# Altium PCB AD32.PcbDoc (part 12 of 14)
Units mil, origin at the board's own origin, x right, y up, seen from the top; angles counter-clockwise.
Board outline 7007.87 x 4368.85 mil, 12 copper layers (Top Layer, Int1 (GND), Int2 (AVDD), Int3 (DVDD), Int4 (GND), Int5 (ST), Int6 (SB), Int8 (AGND), Int7 (AVCC), Int9 (VCCA), Int10 (GND), Bottom Layer), stack 60.136 mil thick; 1350 components, 880 nets, 4712 pads, 2835 vias.
Unrouted connection lines stored in the file: 19.
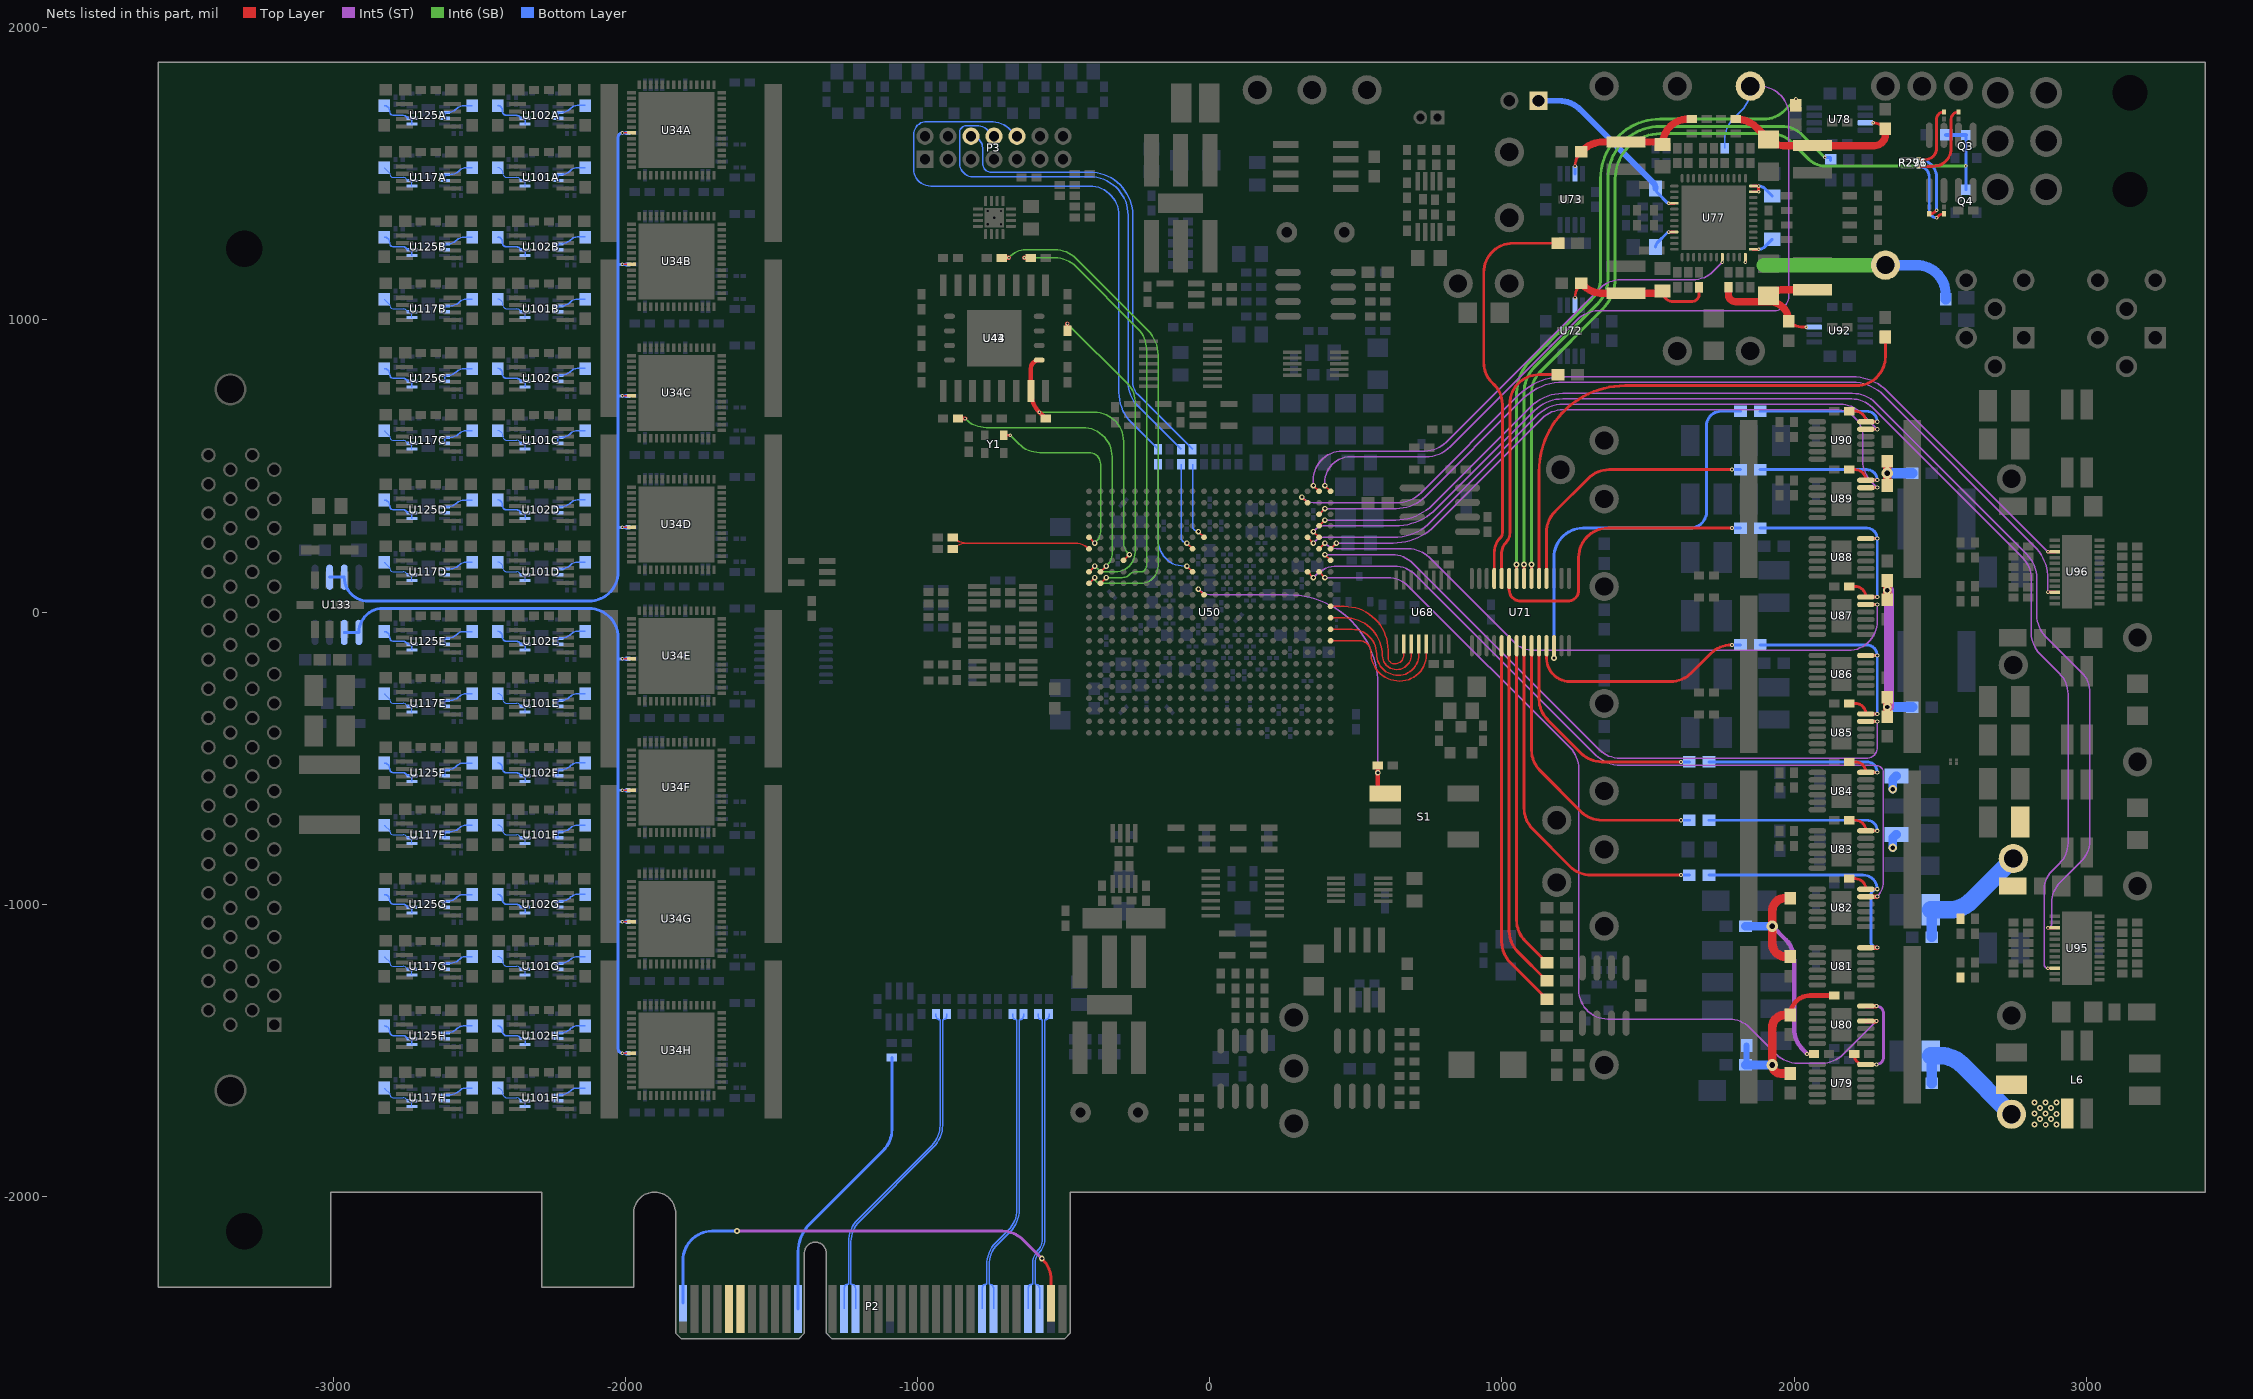
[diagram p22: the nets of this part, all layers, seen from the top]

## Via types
v1: diameter 12, hole 6, Top Layer to Bottom Layer, tented both sides, 1497 vias
v2: diameter 20, hole 10, Top Layer to Bottom Layer, tented both sides, 364 vias
v3: diameter 19, hole 10, Top Layer to Bottom Layer, tented both sides, 347 vias
v4: diameter 14, hole 7, Top Layer to Bottom Layer, tented both sides, 228 vias
v5: diameter 19.68, hole 7.87, Top Layer to Bottom Layer, 225 vias
v6: diameter 19.02, hole 10, Top Layer to Bottom Layer, tented both sides, 85 vias
v7: diameter 20, hole 10, Top Layer to Bottom Layer, 32 vias
v8: diameter 40, hole 20, Top Layer to Bottom Layer, tented both sides, 14 vias
v9: diameter 30, hole 15, Top Layer to Bottom Layer, tented both sides, 12 vias
v10: diameter 25, hole 13, Top Layer to Bottom Layer, 8 vias
v11: diameter 40, hole 20, Top Layer to Bottom Layer, 6 vias
v12: diameter 50, hole 20, Top Layer to Bottom Layer, 6 vias
v13: diameter 66, hole 47, Top Layer to Bottom Layer, tented both sides, 3 vias
v14: diameter 63, hole 45, Top Layer to Bottom Layer, 2 vias
v15: diameter 50, hole 25, Top Layer to Bottom Layer, 2 vias
v16: diameter 12, hole 6, Top Layer to Bottom Layer, 2 vias
v17: diameter 60, hole 40, Top Layer to Bottom Layer, tented both sides, 1 vias
v18: diameter 60, hole 40, Top Layer to Bottom Layer, 1 vias

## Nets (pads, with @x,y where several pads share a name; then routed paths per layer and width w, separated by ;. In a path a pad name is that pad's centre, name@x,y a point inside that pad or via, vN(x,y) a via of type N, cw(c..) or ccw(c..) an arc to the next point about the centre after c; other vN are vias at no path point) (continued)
PER2_N: C277.1 P2.A26 | length 1060.7
  Bottom Layer w4.7: P2.A26@-740.08,-2385 -740.08,-2315.51 ccw(c-755.76,-2315.51) -755.76,-2299.82 -755.76,-2234.68 cw(c-655.76,-2234.68) -726.47,-2163.97 -683.88,-2121.38 ccw(c-760.25,-2045.01) -652.25,-2045.01 -652.25,-1395.81 ccw(c-652.25,-1381.06) -637.5,-1381.06 C277.1@-637.5,-1375.59
PER2_P: C278.1 P2.A25 | length 1060.7
  Bottom Layer w4.7: P2.A25@-779.45,-2385 -779.45,-2315.51 cw(c-763.76,-2315.51) -763.76,-2299.82 -763.76,-2234.68 cw(c-655.76,-2234.68) -732.13,-2158.32 -689.54,-2115.73 ccw(c-760.25,-2045.01) -660.25,-2045.01 -660.25,-1395.81 cw(c-660.25,-1381.06) -675,-1381.06 C278.1@-675,-1375.59
PER3_N: C273.1 P2.A30 | length 1035.6
  Bottom Layer w4.7: P2.A30@-582.6,-2385 -582.6,-2315.51 ccw(c-598.18,-2315.51) -598.18,-2299.92 -598.18,-2227.8 cw(c-544.97,-2227.8) -582.6,-2190.17 ccw(c-625.93,-2146.84) -564.65,-2146.84 -564.65,-1395.71 ccw(c-564.65,-1381.06) -550,-1381.06 C273.1@-550,-1375.59
PER3_P: C276.1 P2.A29 | length 1035.6
  Bottom Layer w4.7: P2.A29@-621.97,-2385 -621.97,-2315.51 cw(c-606.38,-2315.51) -606.38,-2299.92 -606.38,-2227.8 cw(c-544.97,-2227.8) -588.4,-2184.38 ccw(c-625.93,-2146.84) -572.85,-2146.84 -572.85,-1395.71 cw(c-572.85,-1381.06) -587.5,-1381.06 C276.1@-587.5,-1375.59
PERST#: P2.A11 R396.1 | length 982.8
  Bottom Layer w10: P2.A11@-1409.06,-2385 -1409.06,-2190.17 cw(c-1273.57,-2190.17) -1369.37,-2094.37 -1117.38,-1842.38 ccw(c-1188.09,-1771.67) -1088.09,-1771.67 R396.1@-1088.09,-1525
PG0: U50.U1 U89.5 | length 2287.7
  Top Layer w5: U50.U1@413.39,216.54 v3(433.07,236.22)
  Top Layer w10: U89.5@2245.56,425.89 v4(2284.43,425.89)
  Int5 (ST) w5: v3(433.07,236.22) 627.5,236.22 ccw(c627.5,438.34) 770.42,295.42 1138.21,663.21 cw(c1208.92,592.5) 1208.92,692.5 2142.5,692.5 cw(c2142.5,600) 2235,600 2235,516.73 ccw(c2335,516.73) 2264.29,446.02 v4(2284.43,425.89)
PG1: U50.T1 U85.5 | length 2347.4
  Top Layer w5: v3(393.7,196.85) U50.T1@413.39,177.17
  Top Layer w10: U85.5@2245.56,-374.11 v4(2284.43,-374.11)
  Int5 (ST) w5: v3(393.7,196.85) 624.23,196.85 cw(c624.23,96.85) 694.94,167.56 1333.38,-470.88 ccw(c1404.09,-400.17) 1404.09,-500.17 2246.76,-500.17 ccw(c2246.76,-462.5) 2284.43,-462.5 v4(2284.43,-374.11)
PG2: U50.V3 U90.5 | length 2209.8
  Top Layer w5: U50.V3@334.65,255.91 v3(354.33,236.22)
  Top Layer w10: U90.5@2245.56,625.89 v4(2284.43,625.89)
  Int5 (ST) w5: v3(354.33,236.22) 360.1,241.99 cw(c393.7,208.38) 393.7,255.91 629.92,255.91 ccw(c629.92,435.28) 756.76,308.44 1124.87,676.56 cw(c1208.92,592.5) 1208.92,711.37 2157.52,711.37 cw(c2157.52,611.37) 2228.23,682.08 v4(2284.43,625.89)
PG3: U50.Y2 U96.10 | length 3040.6
  Top Layer w5: U50.Y2@374.02,334.65 v3(393.7,354.33) ; v1@2868.75,68.6 v1(2868.75,68.75)
  Top Layer w10: v1@2868.75,68.6 U96.10@2892.25,68.6
  Int5 (ST) w5: v3(393.7,354.33) 468.5,354.33 638.18,354.33 ccw(c638.18,493.7) 736.72,395.15 1071.5,729.92 cw(c1208.92,592.5) 1208.92,786.85 2199.85,786.85 cw(c2199.85,637.74) 2305.29,743.17 2822.46,226 cw(c2710.71,114.25) 2868.75,114.25 v1(2868.75,68.75)
PG4: U50.AA3 U96.3 | length 3015.9
  Top Layer w5: v3(314.96,393.7) U50.AA3@334.65,374.02
  Top Layer w10: v1(2868.75,206.4) U96.3@2892.25,206.4
  Int5 (ST) w5: v3(314.96,393.7) ccw(c362.48,441.22) 362.48,374.02 639.33,374.02 ccw(c639.33,493.7) 723.96,409.07 1058.15,743.27 cw(c1208.92,592.5) 1208.92,805.72 2199.85,805.72 cw(c2199.85,637.74) 2318.63,756.52 v1(2868.75,206.4)
PG5: U50.AB2 U77.20 | length 1797.2
  Top Layer w5: v3(354.33,433.07) U50.AB2@374.02,413.39 ; v1(1754.53,1197.36) U77.20@1754.53,1215.16 v1(1754.53,1197.36)
  Int5 (ST) w5: v3@357.01,435.75 v3(354.33,433.07) 354.33,451.18 cw(c454.33,451.18) 454.33,551.18 735.9,551.18 ccw(c735.9,654.47) 808.93,581.43 1335.71,1108.21 cw(c1406.42,1037.5) 1406.42,1137.5 1653.24,1137.5 ccw(c1653.24,1237.5) 1723.96,1166.79 v1(1754.53,1197.36)
PG6: U50.W2 U95.3 | length 4250.7
  Top Layer w5: U50.W2@374.02,295.28 v3(393.7,314.96)
  Top Layer w10: v1(2868.75,-1081.1) U95.3@2892.25,-1081.1
  Int5 (ST) w5: v3(393.7,314.96) 635.87,314.96 ccw(c635.87,493.7) 762.26,367.31 1097.7,702.76 cw(c1208.44,592.02) 1208.44,748.63 2199.65,748.63 cw(c2199.65,637.26) 2278.4,716.01 2795.58,198.84 cw(c2711.19,114.45) 2830.53,114.45 2830.53,-11.3 ccw(c2930.53,-11.3) 2859.82,-82.01 2983.21,-205.39 cw(c2912.5,-276.11) 3012.5,-276.11 3012.5,-785.38 cw(c2922.88,-785.38) 2986.25,-848.75 2910.54,-924.46 ccw(c2981.25,-995.17) 2881.25,-995.17 2881.25,-1068.6 cw(c2868.75,-1068.6) v1(2868.75,-1081.1)
PG7: U50.V2 U95.10 | length 4360.6
  Top Layer w6: v3(354.33,275.59) U50.V2@374.02,255.91
  Top Layer w10: v1(2868.75,-1218.9) U95.10@2892.25,-1218.9
  Int5 (ST) w5: v3(354.33,275.59) 360.09,281.35 cw(c393.7,247.75) 393.7,295.28 634.71,295.28 ccw(c634.71,493.7) 775.02,353.39 1111.05,689.42 cw(c1208.44,592.02) 1208.44,729.76 2196.55,729.76 cw(c2196.55,629.76) 2267.26,700.47 2782.37,185.36 cw(c2711.66,114.64) 2811.66,114.64 2811.66,-72.2 ccw(c2911.66,-72.2) 2840.95,-142.91 2908.21,-210.17 cw(c2837.5,-280.88) 2937.5,-280.88 2937.5,-789.83 cw(c2837.5,-789.83) 2908.21,-860.54 2881.25,-887.5 ccw(c2941.61,-947.86) 2856.25,-947.86 2856.25,-1206.4 ccw(c2868.75,-1206.4) v1(2868.75,-1218.9)
PG8: U50.R2 U80.4 | length 3161.5
  Top Layer w5: U50.R2@374.02,137.8 v3(393.7,118.11)
  Top Layer w16: U80.4@2245.56,-1399.7 2245.86,-1400 v4(2281.25,-1400)
  Int5 (ST) w5: v3(393.7,118.11) 609.22,118.11 cw(c609.22,18.11) 679.93,88.82 1233.21,-464.46 cw(c1162.5,-535.17) 1262.5,-535.17 1262.5,-1292.91 ccw(c1362.5,-1292.91) 1362.5,-1392.91 1777.74,-1392.91 cw(c1777.74,-1492.91) 1848.45,-1422.2 1940.88,-1514.63 ccw(c2011.59,-1443.92) 2011.59,-1543.92 2095.91,-1543.92 ccw(c2095.91,-1443.92) 2166.62,-1514.63 v4(2281.25,-1400)
PG9: U50.R3 U82.5 | length 2747.1
  Top Layer w5: U50.R3@334.65,137.8 v3(354.33,118.11)
  Top Layer w16: U82.5@2245.56,-974.11 v4(2284.43,-974.11)
  Int5 (ST) w5: v3(354.33,118.11) 364.41,128.19 cw(c435.12,57.48) 435.12,157.48 632.35,157.48 cw(c632.35,57.48) 703.06,128.19 1320.49,-489.24 ccw(c1406.82,-402.9) 1406.82,-525 2279.93,-525 cw(c2279.93,-550.89) 2305.81,-550.89 2305.81,-922.48 cw(c2232.8,-922.48) v4(2284.43,-974.11)
PG10: U50.U2 U87.5 | length 2212.4
  Top Layer w6: U50.U2@374.02,216.54 v3(393.7,236.22)
  Top Layer w10: U87.5@2245.56,25.89 v4(2284.43,25.89)
  Int5 (ST) w5: v3(393.7,236.22) ccw(c441.22,283.74) 441.22,216.54 679.54,216.54 cw(c679.54,116.54) 750.25,187.25 1039.46,-101.96 ccw(c1110.17,-31.25) 1110.17,-131.25 1222.86,-131.25 2184.43,-131.25 ccw(c2184.43,-31.25) 2284.43,-31.25 v4(2284.43,25.89)
POWER.PWRSYNC: R330.2 TP27.1 U50.AB1 | length 2948.5
  Top Layer w6: v3(393.7,433.07) U50.AB1@413.39,413.39
  Int5 (ST) w5: v3(393.7,433.07) 393.7,442.91 cw(c482.28,442.91) 482.28,531.5 738.91,531.5 ccw(c738.91,651.18) 823.54,566.55 1258.95,1001.96 cw(c1329.66,931.25) 1329.66,1031.25 1931.25,1031.25 ccw(c1931.25,1081.25) 1981.25,1081.25 1981.25,1700 ccw(c1881.25,1700) 1881.25,1800 TP27.1@1850,1800
  Bottom Layer w5: R330.2@1762.5,1588.09 1762.5,1617.61 cw(c1862.5,1617.61) 1791.79,1688.32 1820.71,1717.24 ccw(c1750,1787.95) 1850,1787.95 TP27.1@1850,1800
PROG: R379.1 S1.1 U50.N12 | length 1233.3
  Top Layer w5: v3(-39.37,78.74) U50.N12@-19.68,59.06
  Top Layer w15: R379.1@574.41,-525 575,-525.59 575,-598.7 597.56,-621.26 S1.1@600,-621.26
  Int5 (ST) w5: v3(-39.37,78.74) ccw(c8.16,126.27) 8.16,59.06 268.53,59.06 cw(c268.53,-247.41) 575,-247.41 v3(575,-550)
PRSNT1#: P2.A1 P2.B31 | length 1627.9
  Top Layer w10: v2(-575,-2212.5) -572.52,-2214.98 cw(c-643.23,-2285.69) -543.23,-2285.69 P2.B31@-543.23,-2365.31
  Int5 (ST) w10: v2(-1618.75,-2118.75) -710.17,-2118.75 cw(c-710.17,-2218.75) -639.46,-2148.04 v2(-575,-2212.5)
  Bottom Layer w10: P2.A1@-1803.07,-2365.31 -1803.07,-2218.75 cw(c-1703.07,-2218.75) -1703.07,-2118.75 v2(-1618.75,-2118.75)
PUDC_B: R139.1 R140.1 U50.U22 | length 529.8
  Top Layer w5: R139.1@-879.92,216.54 cw(c-832.4,169.01) -832.4,236.22 ; R140.1@-879.92,255.91 ccw(c-832.4,303.43) -832.4,236.22 ; U50.U22@-413.39,216.54 ccw(c-460.91,169.01) -460.91,236.22 -832.4,236.22
QSPI_CS: R155.2 U43.7 U44.1 U50.T19 | length 998.9
  Top Layer w5: U50.T19@-295.28,177.17 v3(-275.59,196.85)
  Top Layer w15: U44.1@-583.96,862.5 ccw(c-583.96,833.96) -612.5,833.96 U43.7@-612.5,756.4 -612.5,754.51 ccw(c-512.5,754.51) v1(-583.21,683.8) R155.2@-561.91,662.5
  Int6 (SB) w5: v1(-583.21,683.8) -395.28,683.8 cw(c-395.28,583.8) -295.28,583.8 -295.28,236.22 ccw(c-247.75,236.22) -281.36,202.62 v3(-275.59,196.85)
QSPI_DQ0: R147.2 U50.P22 | length 1740.2
  Top Layer w5: U50.P22@-413.39,98.43 v3(-393.7,118.11)
  Top Layer w15: R147.2@-711.91,1212.5 v1(-687.5,1212.5)
  Int6 (SB) w5: v1(-687.5,1212.5) -681,1219 cw(c-629.92,1167.92) -629.92,1240.16 -529.61,1240.16 cw(c-529.61,1140.16) -458.9,1210.87 -274.31,1026.28 ; v3(-393.7,118.11) ccw(c-374.02,118.11) -374.02,98.43 -236.22,98.43 ccw(c-236.22,157.48) -177.17,157.48 -177.17,879.64 ccw(c-296.65,879.64) -212.16,964.13 -274.31,1026.28 ; -286.17,1038.14 -274.31,1026.28
QSPI_DQ1: R159.2 U50.R22 | length 1109.8
  Top Layer w5: U50.R22@-413.39,137.8 v3(-393.7,157.48)
  Top Layer w15: R159.2@-487.5,963.09 v1(-487.5,987.7)
  Int6 (SB) w5: v1(-487.5,987.7) -279.71,779.9 cw(c-337.17,722.44) -255.91,722.44 -255.91,205 cw(c-323.11,205) -275.59,157.48 cw(c-323.11,205) -323.11,137.8 -354.33,137.8 cw(c-354.33,185.32) -387.94,151.71 v3(-393.7,157.48)
QSPI_DQ2: R154.2 U50.P21 | length 1509.8
  Top Layer w5: U50.P21@-374.02,98.43 v3(-354.33,118.11)
  Top Layer w15: v1(-635,1212.5) R154.2@-613.09,1212.5
  Int6 (SB) w5: v1(-635,1212.5) -529.51,1212.5 cw(c-529.51,1112.5) -458.8,1183.21 -245.82,970.23 cw(c-316.54,899.52) -216.54,899.52 -216.54,157.48 cw(c-236.22,157.48) -236.22,137.8 -251.83,137.8 ccw(c-251.83,104.19) -275.59,127.95 cw(c-299.35,151.71) -299.35,118.11 v3(-354.33,118.11)
QSPI_DQ3: R141.2 U50.R21 | length 1001
  Top Layer w5: U50.R21@-374.02,137.8 v3(-354.33,157.48)
  Top Layer w15: R141.2@-861.91,662.5 v1(-837.5,662.5)
  Int6 (SB) w5: v1(-837.5,662.5) -835.98,660.98 ccw(c-765.27,731.69) -765.27,631.69 -434.65,631.69 cw(c-434.65,531.69) -334.65,531.69 -334.65,196.85 cw(c-382.17,196.85) -348.57,163.25 v3(-354.33,157.48)
QSPI_EMCLK: U50.V22 Y1.3 | length 678.2
  Top Layer w5: U50.V22@-413.39,255.91 v3(-393.7,236.22)
  Top Layer w10: Y1.3@-705.02,605.31 v1(-683.07,605.31)
  Int6 (SB) w5: v1(-683.07,605.31) -653.21,575.45 ccw(c-582.5,646.16) -582.5,546.16 -413.39,546.16 cw(c-413.39,506.79) -374.02,506.79 -374.02,275.59 cw(c-421.54,275.59) -387.94,241.99 v3(-393.7,236.22)
REF0: C383A.2 C383B.2 C383C.2 C383D.2 U34A.36 U34B.36 U34C.36 U34D.36 U133.6 U133.7 | length 2844.8
  Top Layer w5: v1(-2010.43,290.16) U34D.36@-1979.62,290.16 ; v1(-2010.43,740.16) U34C.36@-1979.62,740.16 ; v1(-2010.43,1190.16) U34B.36@-1979.62,1190.16 ; v1(-2010.43,1640.16) U34A.36@-1979.62,1640.16
  Bottom Layer w10: U133.6@-3012.5,119.49 U133.7@-2962.5,119.49 ccw(c-2880.51,119.49) -2880.51,37.5 -2125,37.5 ccw(c-2125,137.5) -2025,137.5 -2025,290.16 ; C383D.2@-1991.56,290.16 v1(-2010.43,290.16) -2025,290.16 ; C383C.2@-1991.56,740.16 v1(-2010.43,740.16) -2025,740.16 ; C383B.2@-1991.56,1190.16 v1(-2010.43,1190.16) -2025,1190.16 ; C383A.2@-1991.56,1640.16 v1(-2010.43,1640.16) ccw(c-2010.43,1625.59) -2025,1625.59 -2025,1190.16 ; -2025,290.16 -2025,740.16 ; -2025,740.16 -2025,1190.16
REF1: C383E.2 C383F.2 C383G.2 C383H.2 U34E.36 U34F.36 U34G.36 U34H.36 U133.1 U133.2 | length 2714.5
  Top Layer w5: v1(-2010.43,-1509.84) U34H.36@-1979.62,-1509.84 ; v1(-2010.43,-1059.84) U34G.36@-1979.62,-1059.84 ; v1(-2010.43,-609.84) U34F.36@-1979.62,-609.84 ; v1(-2010.43,-159.84) U34E.36@-1979.62,-159.84
  Bottom Layer w10: U133.2@-2962.5,-69.49 U133.1@-2912.5,-69.49 cw(c-2830.51,-69.49) -2830.51,12.5 -2125,12.5 cw(c-2125,-87.5) -2025,-87.5 -2025,-159.84 ; C383H.2@-1991.56,-1509.84 v1(-2010.43,-1509.84) cw(c-2010.43,-1495.27) -2025,-1495.27 -2025,-1059.84 ; C383G.2@-1991.56,-1059.84 v1(-2010.43,-1059.84) -2025,-1059.84 ; C383F.2@-1991.56,-609.84 v1(-2010.43,-609.84) -2025,-609.84 ; C383E.2@-1991.56,-159.84 v1(-2010.43,-159.84) -2025,-159.84 ; -2025,-1059.84 -2025,-609.84 ; -2025,-609.84 -2025,-159.84
REFCLK_N: C284.1 P2.A14 | length 1147.6
  Bottom Layer w4.7: P2.A14@-1212.52,-2385 -1212.52,-2315.51 ccw(c-1228.2,-2315.51) -1228.2,-2299.82 -1228.2,-2155.45 cw(c-1128.2,-2155.45) -1198.92,-2084.74 -946.08,-1831.91 ccw(c-1022.45,-1755.54) -914.45,-1755.54 -914.45,-1395.41 ccw(c-914.45,-1380.96) -900,-1380.96 C284.1@-900,-1375.59
REFCLK_P: C286.1 P2.A13 | length 1147.4
  Bottom Layer w4.7: P2.A13@-1251.89,-2385 -1251.89,-2315.51 cw(c-1236.2,-2315.51) -1236.2,-2299.82 -1236.2,-2155.45 cw(c-1128.2,-2155.45) -1204.57,-2079.09 -952.34,-1826.85 ccw(c-1023.05,-1756.14) -923.05,-1756.14 -923.05,-1395.41 cw(c-923.05,-1380.96) -937.5,-1380.96 C286.1@-937.5,-1375.59
S1NA: R609A.1 U125A.6 U125A.7 | length 119.9
  Bottom Layer w5: U125A.7@-2618.89,1690.03 U125A.6@-2618.89,1709.72 -2611.9,1709.72 ccw(c-2611.9,1761.9) -2575,1725 cw(c-2554.87,1704.87) -2554.87,1733.34 R609A.1@-2525,1733.34
S1NB: R609B.1 U125B.6 U125B.7 | length 119.9
  Bottom Layer w5: U125B.7@-2618.89,1240.03 U125B.6@-2618.89,1259.72 -2611.9,1259.72 ccw(c-2611.9,1311.9) -2575,1275 cw(c-2554.87,1254.87) -2554.87,1283.34 R609B.1@-2525,1283.34
S1NC: R609C.1 U125C.6 U125C.7 | length 119.9
  Bottom Layer w5: U125C.7@-2618.89,790.03 U125C.6@-2618.89,809.72 -2611.9,809.72 ccw(c-2611.9,861.9) -2575,825 cw(c-2554.87,804.87) -2554.87,833.34 R609C.1@-2525,833.34
S1ND: R609D.1 U125D.6 U125D.7 | length 119.9
  Bottom Layer w5: U125D.7@-2618.89,340.03 U125D.6@-2618.89,359.72 -2611.9,359.72 ccw(c-2611.9,411.9) -2575,375 cw(c-2554.87,354.87) -2554.87,383.34 R609D.1@-2525,383.34
S1NE: R609E.1 U125E.6 U125E.7 | length 119.9
  Bottom Layer w5: U125E.7@-2618.89,-109.97 U125E.6@-2618.89,-90.28 -2611.9,-90.28 ccw(c-2611.9,-38.1) -2575,-75 cw(c-2554.87,-95.13) -2554.87,-66.66 R609E.1@-2525,-66.66
S1NF: R609F.1 U125F.6 U125F.7 | length 119.9
  Bottom Layer w5: U125F.7@-2618.89,-559.97 U125F.6@-2618.89,-540.28 -2611.9,-540.28 ccw(c-2611.9,-488.1) -2575,-525 cw(c-2554.87,-545.13) -2554.87,-516.66 R609F.1@-2525,-516.66
S1NG: R609G.1 U125G.6 U125G.7 | length 119.9
  Bottom Layer w5: U125G.7@-2618.89,-1009.97 U125G.6@-2618.89,-990.28 -2611.9,-990.28 ccw(c-2611.9,-938.1) -2575,-975 cw(c-2554.87,-995.13) -2554.87,-966.66 R609G.1@-2525,-966.66
S1NH: R609H.1 U125H.6 U125H.7 | length 119.9
  Bottom Layer w5: U125H.7@-2618.89,-1459.97 U125H.6@-2618.89,-1440.28 -2611.9,-1440.28 ccw(c-2611.9,-1388.1) -2575,-1425 cw(c-2554.87,-1445.13) -2554.87,-1416.66 R609H.1@-2525,-1416.66
S1PA: R657A.1 U125A.1 U125A.2 | length 137.4
  Bottom Layer w5: R657A.1@-2825,1733.34 cw(c-2825,1715.84) R657A.1@-2807.5,1715.84 ; U125A.1@-2731.1,1670.35 U125A.2@-2731.1,1690.03 -2736.39,1690.03 cw(c-2736.39,1709.28) -2750,1695.67 ccw(c-2760.15,1685.52) -2760.15,1699.87 -2792.37,1699.87 cw(c-2792.37,1715) R657A.1@-2807.5,1715 ; R657A.1@-2807.5,1715 R657A.1@-2807.5,1715.84 ; R657A.1@-2807.5,1715 R657A.1@-2807.5,1715.84 ; R657A.1@-2807.5,1715 R657A.1@-2807.5,1715.84
S1PB: R657B.1 U125B.1 U125B.2 | length 137.4
  Bottom Layer w5: R657B.1@-2825,1283.34 cw(c-2825,1265.84) R657B.1@-2807.5,1265.84 ; U125B.1@-2731.1,1220.35 U125B.2@-2731.1,1240.03 -2736.39,1240.03 cw(c-2736.39,1259.28) -2750,1245.67 ccw(c-2760.15,1235.52) -2760.15,1249.87 -2792.37,1249.87 cw(c-2792.37,1265) R657B.1@-2807.5,1265 ; R657B.1@-2807.5,1265 R657B.1@-2807.5,1265.84 ; R657B.1@-2807.5,1265 R657B.1@-2807.5,1265.84 ; R657B.1@-2807.5,1265 R657B.1@-2807.5,1265.84
S1PC: R657C.1 U125C.1 U125C.2 | length 137.4
  Bottom Layer w5: R657C.1@-2825,833.34 cw(c-2825,815.84) R657C.1@-2807.5,815.84 ; U125C.1@-2731.1,770.35 U125C.2@-2731.1,790.03 -2736.39,790.03 cw(c-2736.39,809.28) -2750,795.67 ccw(c-2760.15,785.52) -2760.15,799.87 -2792.37,799.87 cw(c-2792.37,815) R657C.1@-2807.5,815 ; R657C.1@-2807.5,815 R657C.1@-2807.5,815.84 ; R657C.1@-2807.5,815 R657C.1@-2807.5,815.84 ; R657C.1@-2807.5,815 R657C.1@-2807.5,815.84
S1PD: R657D.1 U125D.1 U125D.2 | length 137.4
  Bottom Layer w5: R657D.1@-2825,383.34 cw(c-2825,365.84) R657D.1@-2807.5,365.84 ; U125D.1@-2731.1,320.35 U125D.2@-2731.1,340.03 -2736.39,340.03 cw(c-2736.39,359.28) -2750,345.67 ccw(c-2760.15,335.52) -2760.15,349.87 -2792.37,349.87 cw(c-2792.37,365) R657D.1@-2807.5,365 ; R657D.1@-2807.5,365 R657D.1@-2807.5,365.84 ; R657D.1@-2807.5,365 R657D.1@-2807.5,365.84 ; R657D.1@-2807.5,365 R657D.1@-2807.5,365.84
S1PE: R657E.1 U125E.1 U125E.2 | length 137.4
  Bottom Layer w5: R657E.1@-2825,-66.66 cw(c-2825,-84.16) R657E.1@-2807.5,-84.16 ; U125E.1@-2731.1,-129.65 U125E.2@-2731.1,-109.97 -2736.39,-109.97 cw(c-2736.39,-90.72) -2750,-104.33 ccw(c-2760.15,-114.48) -2760.15,-100.13 -2792.37,-100.13 cw(c-2792.37,-85) R657E.1@-2807.5,-85 ; R657E.1@-2807.5,-85 R657E.1@-2807.5,-84.16 ; R657E.1@-2807.5,-85 R657E.1@-2807.5,-84.16 ; R657E.1@-2807.5,-85 R657E.1@-2807.5,-84.16
S1PF: R657F.1 U125F.1 U125F.2 | length 137.4
  Bottom Layer w5: R657F.1@-2825,-516.66 cw(c-2825,-534.16) R657F.1@-2807.5,-534.16 ; U125F.1@-2731.1,-579.65 U125F.2@-2731.1,-559.97 -2736.39,-559.97 cw(c-2736.39,-540.72) -2750,-554.33 ccw(c-2760.15,-564.48) -2760.15,-550.13 -2792.37,-550.13 cw(c-2792.37,-535) R657F.1@-2807.5,-535 ; R657F.1@-2807.5,-535 R657F.1@-2807.5,-534.16 ; R657F.1@-2807.5,-535 R657F.1@-2807.5,-534.16 ; R657F.1@-2807.5,-535 R657F.1@-2807.5,-534.16
S1PG: R657G.1 U125G.1 U125G.2 | length 137.4
  Bottom Layer w5: R657G.1@-2825,-966.66 cw(c-2825,-984.16) R657G.1@-2807.5,-984.16 ; U125G.1@-2731.1,-1029.65 U125G.2@-2731.1,-1009.97 -2736.39,-1009.97 cw(c-2736.39,-990.72) -2750,-1004.33 ccw(c-2760.15,-1014.48) -2760.15,-1000.13 -2792.37,-1000.13 cw(c-2792.37,-985) R657G.1@-2807.5,-985 ; R657G.1@-2807.5,-985 R657G.1@-2807.5,-984.16 ; R657G.1@-2807.5,-985 R657G.1@-2807.5,-984.16 ; R657G.1@-2807.5,-985 R657G.1@-2807.5,-984.16
S1PH: R657H.1 U125H.1 U125H.2 | length 135.7
  Bottom Layer w5: R657H.1@-2825,-1416.66 cw(c-2825,-1434.16) -2807.5,-1434.16 -2807.5,-1435 ccw(c-2792.37,-1435) -2792.37,-1450.13 -2760.15,-1450.13 cw(c-2760.15,-1464.48) -2750,-1454.33 ccw(c-2736.39,-1440.72) -2736.39,-1459.97 U125H.2@-2731.1,-1459.97 U125H.1@-2731.1,-1479.65
S2NA: R538A.1 U102A.6 U102A.7 | length 120
  Bottom Layer w5: U102A.7@-2231.39,1690.16 U102A.6@-2231.39,1709.84 -2223.09,1709.84 ccw(c-2223.09,1761.59) -2186.5,1725 cw(c-2164.86,1703.36) -2164.86,1733.96 R538A.1@-2137.5,1733.96
S2NB: R538B.1 U102B.6 U102B.7 | length 120
  Bottom Layer w5: U102B.7@-2231.39,1240.16 U102B.6@-2231.39,1259.84 -2223.09,1259.84 ccw(c-2223.09,1311.59) -2186.5,1275 cw(c-2164.86,1253.36) -2164.86,1283.96 R538B.1@-2137.5,1283.96
S2NC: R538C.1 U102C.6 U102C.7 | length 120
  Bottom Layer w5: U102C.7@-2231.39,790.16 U102C.6@-2231.39,809.84 -2223.09,809.84 ccw(c-2223.09,861.59) -2186.5,825 cw(c-2164.86,803.36) -2164.86,833.96 R538C.1@-2137.5,833.96
S2ND: R538D.1 U102D.6 U102D.7 | length 120
  Bottom Layer w5: U102D.7@-2231.39,340.16 U102D.6@-2231.39,359.84 -2223.09,359.84 ccw(c-2223.09,411.59) -2186.5,375 cw(c-2164.86,353.36) -2164.86,383.96 R538D.1@-2137.5,383.96
S2NE: R538E.1 U102E.6 U102E.7 | length 120
  Bottom Layer w5: U102E.7@-2231.39,-109.84 U102E.6@-2231.39,-90.16 -2223.09,-90.16 ccw(c-2223.09,-38.41) -2186.5,-75 cw(c-2164.86,-96.64) -2164.86,-66.04 R538E.1@-2137.5,-66.04
S2NF: R538F.1 U102F.6 U102F.7 | length 120
  Bottom Layer w5: U102F.7@-2231.39,-559.84 U102F.6@-2231.39,-540.16 -2223.09,-540.16 ccw(c-2223.09,-488.41) -2186.5,-525 cw(c-2164.86,-546.64) -2164.86,-516.04 R538F.1@-2137.5,-516.04
S2NG: R538G.1 U102G.6 U102G.7 | length 120
  Bottom Layer w5: U102G.7@-2231.39,-1009.84 U102G.6@-2231.39,-990.16 -2223.09,-990.16 ccw(c-2223.09,-938.41) -2186.5,-975 cw(c-2164.86,-996.64) -2164.86,-966.04 R538G.1@-2137.5,-966.04
S2NH: R538H.1 U102H.6 U102H.7 | length 120
  Bottom Layer w5: U102H.7@-2231.39,-1459.84 U102H.6@-2231.39,-1440.16 -2223.09,-1440.16 ccw(c-2223.09,-1388.41) -2186.5,-1425 cw(c-2164.86,-1446.64) -2164.86,-1416.04 R538H.1@-2137.5,-1416.04
S2PA: R593A.1 U102A.1 U102A.2 | length 136.9
  Bottom Layer w5: R593A.1@-2437.5,1733.96 cw(c-2437.5,1717.96) -2421.5,1717.96 -2421.5,1715 ccw(c-2406.37,1715) -2406.37,1699.87 -2372.76,1699.87 cw(c-2372.76,1685.09) -2362.31,1695.54 ccw(c-2349.3,1708.55) -2349.3,1690.16 U102A.2@-2343.6,1690.16 U102A.1@-2343.6,1670.47
S2PB: R593B.1 U102B.1 U102B.2 | length 136.9
  Bottom Layer w5: R593B.1@-2437.5,1283.96 cw(c-2437.5,1267.96) -2421.5,1267.96 -2421.5,1265 ccw(c-2406.37,1265) -2406.37,1249.87 -2372.76,1249.87 cw(c-2372.76,1235.09) -2362.31,1245.54 ccw(c-2349.3,1258.55) -2349.3,1240.16 U102B.2@-2343.6,1240.16 U102B.1@-2343.6,1220.47
S2PC: R593C.1 U102C.1 U102C.2 | length 136.9
  Bottom Layer w5: R593C.1@-2437.5,833.96 cw(c-2437.5,817.96) -2421.5,817.96 -2421.5,815 ccw(c-2406.37,815) -2406.37,799.87 -2372.76,799.87 cw(c-2372.76,785.09) -2362.31,795.54 ccw(c-2349.3,808.55) -2349.3,790.16 U102C.2@-2343.6,790.16 U102C.1@-2343.6,770.47
S2PD: R593D.1 U102D.1 U102D.2 | length 136.9
  Bottom Layer w5: R593D.1@-2437.5,383.96 cw(c-2437.5,367.96) -2421.5,367.96 -2421.5,365 ccw(c-2406.37,365) -2406.37,349.87 -2372.76,349.87 cw(c-2372.76,335.09) -2362.31,345.54 ccw(c-2349.3,358.55) -2349.3,340.16 U102D.2@-2343.6,340.16 U102D.1@-2343.6,320.47
S2PE: R593E.1 U102E.1 U102E.2 | length 136.9
  Bottom Layer w5: R593E.1@-2437.5,-66.04 cw(c-2437.5,-82.04) -2421.5,-82.04 -2421.5,-85 ccw(c-2406.37,-85) -2406.37,-100.13 -2372.76,-100.13 cw(c-2372.76,-114.91) -2362.31,-104.46 ccw(c-2349.3,-91.45) -2349.3,-109.84 U102E.2@-2343.6,-109.84 U102E.1@-2343.6,-129.53
S2PF: R593F.1 U102F.1 U102F.2 | length 136.9
  Bottom Layer w5: R593F.1@-2437.5,-516.04 cw(c-2437.5,-532.04) -2421.5,-532.04 -2421.5,-535 ccw(c-2406.37,-535) -2406.37,-550.13 -2372.76,-550.13 cw(c-2372.76,-564.91) -2362.31,-554.46 ccw(c-2349.3,-541.45) -2349.3,-559.84 U102F.2@-2343.6,-559.84 U102F.1@-2343.6,-579.53
S2PG: R593G.1 U102G.1 U102G.2 | length 136.9
  Bottom Layer w5: R593G.1@-2437.5,-966.04 cw(c-2437.5,-982.04) -2421.5,-982.04 -2421.5,-985 ccw(c-2406.37,-985) -2406.37,-1000.13 -2372.76,-1000.13 cw(c-2372.76,-1014.91) -2362.31,-1004.46 ccw(c-2349.3,-991.45) -2349.3,-1009.84 U102G.2@-2343.6,-1009.84 U102G.1@-2343.6,-1029.53
S2PH: R593H.1 U102H.1 U102H.2 | length 136.9
  Bottom Layer w5: R593H.1@-2437.5,-1416.04 cw(c-2437.5,-1432.04) -2421.5,-1432.04 -2421.5,-1435 ccw(c-2406.37,-1435) -2406.37,-1450.13 -2372.76,-1450.13 cw(c-2372.76,-1464.91) -2362.31,-1454.46 ccw(c-2349.3,-1441.45) -2349.3,-1459.84 U102H.2@-2343.6,-1459.84 U102H.1@-2343.6,-1479.53
S3NA: R601A.1 U117A.6 U117A.7 | length 119.9
  Bottom Layer w5: U117A.7@-2618.89,1477.66 U117A.6@-2618.89,1497.34 -2603.66,1497.34 ccw(c-2603.66,1549.09) -2578.12,1504.08 ccw(c-2603.66,1549.09) -2567.06,1512.5 cw(c-2546.63,1492.07) -2546.63,1520.96 R601A.1@-2525,1520.96
S3NB: R601B.1 U117B.6 U117B.7 | length 119.9
  Bottom Layer w5: U117B.7@-2618.89,1027.66 U117B.6@-2618.89,1047.34 -2603.66,1047.34 ccw(c-2603.66,1099.09) -2578.12,1054.08 ccw(c-2603.66,1099.09) -2567.06,1062.5 cw(c-2546.63,1042.07) -2546.63,1070.96 R601B.1@-2525,1070.96
S3NC: R601C.1 U117C.6 U117C.7 | length 119.9
  Bottom Layer w5: U117C.7@-2618.89,577.66 U117C.6@-2618.89,597.34 -2603.66,597.34 ccw(c-2603.66,649.09) -2578.12,604.08 ccw(c-2603.66,649.09) -2567.06,612.5 cw(c-2546.63,592.07) -2546.63,620.96 R601C.1@-2525,620.96
S3ND: R601D.1 U117D.6 U117D.7 | length 119.9
  Bottom Layer w5: U117D.7@-2618.89,127.66 U117D.6@-2618.89,147.34 -2603.66,147.34 ccw(c-2603.66,199.09) -2578.12,154.08 ccw(c-2603.66,199.09) -2567.06,162.5 cw(c-2546.63,142.07) -2546.63,170.96 R601D.1@-2525,170.96
S3NE: R601E.1 U117E.6 U117E.7 | length 119.9
  Bottom Layer w5: U117E.7@-2618.89,-322.34 U117E.6@-2618.89,-302.66 -2603.66,-302.66 ccw(c-2603.66,-250.91) -2578.12,-295.92 ccw(c-2603.66,-250.91) -2567.06,-287.5 cw(c-2546.63,-307.93) -2546.63,-279.04 R601E.1@-2525,-279.04
S3NF: R601F.1 U117F.6 U117F.7 | length 119.9
  Bottom Layer w5: U117F.7@-2618.89,-772.34 U117F.6@-2618.89,-752.66 -2603.66,-752.66 ccw(c-2603.66,-700.91) -2578.12,-745.92 ccw(c-2603.66,-700.91) -2567.06,-737.5 cw(c-2546.63,-757.93) -2546.63,-729.04 R601F.1@-2525,-729.04
S3NG: R601G.1 U117G.6 U117G.7 | length 119.9
  Bottom Layer w5: U117G.7@-2618.89,-1222.34 U117G.6@-2618.89,-1202.66 -2603.66,-1202.66 ccw(c-2603.66,-1150.91) -2578.12,-1195.92 ccw(c-2603.66,-1150.91) -2567.06,-1187.5 cw(c-2546.63,-1207.93) -2546.63,-1179.04 R601G.1@-2525,-1179.04
S3NH: R601H.1 U117H.6 U117H.7 | length 119.9
  Bottom Layer w5: U117H.7@-2618.89,-1672.34 U117H.6@-2618.89,-1652.66 -2603.66,-1652.66 ccw(c-2603.66,-1600.91) -2578.12,-1645.92 ccw(c-2603.66,-1600.91) -2567.06,-1637.5 cw(c-2546.63,-1657.93) -2546.63,-1629.04 R601H.1@-2525,-1629.04
S3PA: R649A.1 U117A.1 U117A.2 | length 132.9
  Bottom Layer w4: R649A.1@-2825,1520.96 ccw(c-2822.67,1520.96) -2824.32,1519.32 -2807.5,1502.5 ccw(c-2792.5,1502.5) -2792.5,1487.5 -2760.45,1487.5 cw(c-2760.45,1472.71) -2750,1483.17 ccw(c-2736.69,1496.48) -2736.69,1477.66 U117A.2@-2731.1,1477.66 U117A.1@-2731.1,1457.97
S3PB: R649B.1 U117B.1 U117B.2 | length 132.9
  Bottom Layer w4: R649B.1@-2825,1070.96 ccw(c-2822.67,1070.96) -2824.32,1069.32 -2807.5,1052.5 ccw(c-2792.5,1052.5) -2792.5,1037.5 -2760.45,1037.5 cw(c-2760.45,1022.71) -2750,1033.17 ccw(c-2736.69,1046.48) -2736.69,1027.66 U117B.2@-2731.1,1027.66 U117B.1@-2731.1,1007.97
S3PC: R649C.1 U117C.1 U117C.2 | length 132.9
  Bottom Layer w4: R649C.1@-2825,620.96 ccw(c-2822.67,620.96) -2824.32,619.32 -2807.5,602.5 ccw(c-2792.5,602.5) -2792.5,587.5 -2760.45,587.5 cw(c-2760.45,572.71) -2750,583.17 ccw(c-2736.69,596.48) -2736.69,577.66 U117C.2@-2731.1,577.66 U117C.1@-2731.1,557.97
S3PD: R649D.1 U117D.1 U117D.2 | length 132.9
  Bottom Layer w4: R649D.1@-2825,170.96 ccw(c-2822.67,170.96) -2824.32,169.32 -2807.5,152.5 ccw(c-2792.5,152.5) -2792.5,137.5 -2760.45,137.5 cw(c-2760.45,122.71) -2750,133.17 ccw(c-2736.69,146.48) -2736.69,127.66 U117D.2@-2731.1,127.66 U117D.1@-2731.1,107.97
S3PE: R649E.1 U117E.1 U117E.2 | length 132.9
  Bottom Layer w4: R649E.1@-2825,-279.04 ccw(c-2822.67,-279.04) -2824.32,-280.68 -2807.5,-297.5 ccw(c-2792.5,-297.5) -2792.5,-312.5 -2760.45,-312.5 cw(c-2760.45,-327.29) -2750,-316.83 ccw(c-2736.69,-303.52) -2736.69,-322.34 U117E.2@-2731.1,-322.34 U117E.1@-2731.1,-342.03
S3PF: R649F.1 U117F.1 U117F.2 | length 132.9
  Bottom Layer w4: R649F.1@-2825,-729.04 ccw(c-2822.67,-729.04) -2824.32,-730.68 -2807.5,-747.5 ccw(c-2792.5,-747.5) -2792.5,-762.5 -2760.45,-762.5 cw(c-2760.45,-777.29) -2750,-766.83 ccw(c-2736.69,-753.52) -2736.69,-772.34 U117F.2@-2731.1,-772.34 U117F.1@-2731.1,-792.03
S3PG: R649G.1 U117G.1 U117G.2 | length 132.9
  Bottom Layer w4: R649G.1@-2825,-1179.04 ccw(c-2822.67,-1179.04) -2824.32,-1180.68 -2807.5,-1197.5 ccw(c-2792.5,-1197.5) -2792.5,-1212.5 -2760.45,-1212.5 cw(c-2760.45,-1227.29) -2750,-1216.83 ccw(c-2736.69,-1203.52) -2736.69,-1222.34 U117G.2@-2731.1,-1222.34 U117G.1@-2731.1,-1242.03
S3PH: R649H.1 U117H.1 U117H.2 | length 132.9
  Bottom Layer w4: R649H.1@-2825,-1629.04 ccw(c-2822.67,-1629.04) -2824.32,-1630.68 -2807.5,-1647.5 ccw(c-2792.5,-1647.5) -2792.5,-1662.5 -2760.45,-1662.5 cw(c-2760.45,-1677.29) -2750,-1666.83 ccw(c-2736.69,-1653.52) -2736.69,-1672.34 U117H.2@-2731.1,-1672.34 U117H.1@-2731.1,-1692.03
S4NA: R537A.1 U101A.6 U101A.7 | length 119.9
  Bottom Layer w5: U101A.7@-2231.39,1477.66 U101A.6@-2231.39,1497.34 -2223.16,1497.34 ccw(c-2223.16,1547.77) -2187.5,1512.11 cw(c-2166.13,1490.74) -2166.13,1520.96 R537A.1@-2137.5,1520.96
S4NB: R537B.1 U101B.6 U101B.7 | length 119.9
  Bottom Layer w5: U101B.7@-2231.39,1027.66 U101B.6@-2231.39,1047.34 -2223.16,1047.34 ccw(c-2223.16,1097.77) -2187.5,1062.11 cw(c-2166.13,1040.74) -2166.13,1070.96 R537B.1@-2137.5,1070.96
S4NC: R537C.1 U101C.6 U101C.7 | length 119.9
  Bottom Layer w5: U101C.7@-2231.39,577.66 U101C.6@-2231.39,597.34 -2223.16,597.34 ccw(c-2223.16,647.77) -2187.5,612.11 cw(c-2166.13,590.74) -2166.13,620.96 R537C.1@-2137.5,620.96
S4ND: R537D.1 U101D.6 U101D.7 | length 119.9
  Bottom Layer w5: U101D.7@-2231.39,127.66 U101D.6@-2231.39,147.34 -2223.16,147.34 ccw(c-2223.16,197.77) -2187.5,162.11 cw(c-2166.13,140.74) -2166.13,170.96 R537D.1@-2137.5,170.96
S4NE: R537E.1 U101E.6 U101E.7 | length 119.9
  Bottom Layer w5: U101E.7@-2231.39,-322.34 U101E.6@-2231.39,-302.66 -2223.16,-302.66 ccw(c-2223.16,-252.23) -2187.5,-287.89 cw(c-2166.13,-309.26) -2166.13,-279.04 R537E.1@-2137.5,-279.04
S4NF: R537F.1 U101F.6 U101F.7 | length 119.9
  Bottom Layer w5: U101F.7@-2231.39,-772.34 U101F.6@-2231.39,-752.66 -2223.16,-752.66 ccw(c-2223.16,-702.23) -2187.5,-737.89 cw(c-2166.13,-759.26) -2166.13,-729.04 R537F.1@-2137.5,-729.04
S4NG: R537G.1 U101G.6 U101G.7 | length 119.9
  Bottom Layer w5: U101G.7@-2231.39,-1222.34 U101G.6@-2231.39,-1202.66 -2223.16,-1202.66 ccw(c-2223.16,-1152.23) -2187.5,-1187.89 cw(c-2166.13,-1209.26) -2166.13,-1179.04 R537G.1@-2137.5,-1179.04
S4NH: R537H.1 U101H.6 U101H.7 | length 119.9
  Bottom Layer w5: U101H.7@-2231.39,-1672.34 U101H.6@-2231.39,-1652.66 -2223.16,-1652.66 ccw(c-2223.16,-1602.23) -2187.5,-1637.89 cw(c-2166.13,-1659.26) -2166.13,-1629.04 R537H.1@-2137.5,-1629.04
S4PA: R585A.1 U101A.1 U101A.2 | length 135.7
  Bottom Layer w4: R585A.1@-2437.5,1520.96 cw(c-2437.5,1503.46) -2420,1503.46 -2420,1502.5 ccw(c-2405,1502.5) -2405,1487.5 -2372.11,1487.5 cw(c-2372.11,1473.64) -2362.31,1483.44 ccw(c-2348.34,1497.4) -2348.34,1477.66 U101A.2@-2343.6,1477.66 U101A.1@-2343.6,1457.97
S4PB: R585B.1 U101B.1 U101B.2 | length 135.7
  Bottom Layer w4: R585B.1@-2437.5,1070.96 cw(c-2437.5,1053.46) -2420,1053.46 -2420,1052.5 ccw(c-2405,1052.5) -2405,1037.5 -2372.11,1037.5 cw(c-2372.11,1023.64) -2362.31,1033.44 ccw(c-2348.34,1047.4) -2348.34,1027.66 U101B.2@-2343.6,1027.66 U101B.1@-2343.6,1007.97
S4PC: R585C.1 U101C.1 U101C.2 | length 135.7
  Bottom Layer w4: R585C.1@-2437.5,620.96 cw(c-2437.5,603.46) -2420,603.46 -2420,602.5 ccw(c-2405,602.5) -2405,587.5 -2372.11,587.5 cw(c-2372.11,573.64) -2362.31,583.44 ccw(c-2348.34,597.4) -2348.34,577.66 U101C.2@-2343.6,577.66 U101C.1@-2343.6,557.97
S4PD: R585D.1 U101D.1 U101D.2 | length 135.7
  Bottom Layer w4: R585D.1@-2437.5,170.96 cw(c-2437.5,153.46) -2420,153.46 -2420,152.5 ccw(c-2405,152.5) -2405,137.5 -2372.11,137.5 cw(c-2372.11,123.64) -2362.31,133.44 ccw(c-2348.34,147.4) -2348.34,127.66 U101D.2@-2343.6,127.66 U101D.1@-2343.6,107.97
S4PE: R585E.1 U101E.1 U101E.2 | length 135.7
  Bottom Layer w4: R585E.1@-2437.5,-279.04 cw(c-2437.5,-296.54) -2420,-296.54 -2420,-297.5 ccw(c-2405,-297.5) -2405,-312.5 -2372.11,-312.5 cw(c-2372.11,-326.36) -2362.31,-316.56 ccw(c-2348.34,-302.6) -2348.34,-322.34 U101E.2@-2343.6,-322.34 U101E.1@-2343.6,-342.03
S4PF: R585F.1 U101F.1 U101F.2 | length 135.7
  Bottom Layer w4: R585F.1@-2437.5,-729.04 cw(c-2437.5,-746.54) -2420,-746.54 -2420,-747.5 ccw(c-2405,-747.5) -2405,-762.5 -2372.11,-762.5 cw(c-2372.11,-776.36) -2362.31,-766.56 ccw(c-2348.34,-752.6) -2348.34,-772.34 U101F.2@-2343.6,-772.34 U101F.1@-2343.6,-792.03
S4PG: R585G.1 U101G.1 U101G.2 | length 135.7
  Bottom Layer w4: R585G.1@-2437.5,-1179.04 cw(c-2437.5,-1196.54) -2420,-1196.54 -2420,-1197.5 ccw(c-2405,-1197.5) -2405,-1212.5 -2372.11,-1212.5 cw(c-2372.11,-1226.36) -2362.31,-1216.56 ccw(c-2348.34,-1202.6) -2348.34,-1222.34 U101G.2@-2343.6,-1222.34 U101G.1@-2343.6,-1242.03
S4PH: R585H.1 U101H.1 U101H.2 | length 135.7
  Bottom Layer w4: R585H.1@-2437.5,-1629.04 cw(c-2437.5,-1646.54) -2420,-1646.54 -2420,-1647.5 ccw(c-2405,-1647.5) -2405,-1662.5 -2372.11,-1662.5 cw(c-2372.11,-1676.36) -2362.31,-1666.56 ccw(c-2348.34,-1652.6) -2348.34,-1672.34 U101H.2@-2343.6,-1672.34 U101H.1@-2343.6,-1692.03
SENS1: R199.2 U71.19 | length 1269.8
  Top Layer w10: U71.19@999.02,-115.16 999.02,-1128.56 ccw(c1099.02,-1128.56) 1028.31,-1199.27 R199.2@1154.04,-1325
SENS2: R200.2 U71.20 | length 1196.7
  Top Layer w10: U71.20@1024.61,-115.16 1024.61,-1091.65 ccw(c1124.61,-1091.65) 1053.9,-1162.36 R200.2@1154.04,-1262.5
SENS3: R201.2 U71.21 | length 1123.6
  Top Layer w10: U71.21@1050,-115.16 1050,-1054.54 ccw(c1150,-1054.54) 1079.29,-1125.25 R201.2@1154.04,-1200
SENS4: R332.2 U71.22 | length 1232.6
  Top Layer w10: U71.22@1075.79,-115.16 1075.79,-671.87 ccw(c1175.79,-671.87) 1105.08,-742.58 1233.21,-870.71 ccw(c1303.92,-800) 1303.92,-900 v4(1612.5,-900)
  Bottom Layer w10: v4(1612.5,-900) R332.2@1641.54,-900
SENS5: R333.2 U71.23 | length 1012.5
  Top Layer w10: U71.23@1101.38,-115.16 1101.38,-472.46 ccw(c1201.38,-472.46) 1130.67,-543.17 1270.71,-683.21 ccw(c1341.42,-612.5) 1341.42,-712.5 v4(1612.5,-712.5)
  Bottom Layer w10: v4(1612.5,-712.5) R333.2@1641.54,-712.5
SENS6: R334.2 U71.24 | length 801.8
  Top Layer w10: U71.24@1126.97,-115.16 1126.97,-297.85 ccw(c1226.97,-297.85) 1156.26,-368.56 1270.91,-483.21 ccw(c1341.62,-412.5) 1341.62,-512.5 v4(1612.5,-512.5)
  Bottom Layer w10: v4(1612.5,-512.5) R334.2@1641.54,-512.5
SENS7: R320.2 U71.25 | length 795.1
  Top Layer w10: U71.25@1152.56,-115.16 1152.56,-157.48 ccw(c1232.58,-157.48) 1232.58,-237.5 1577.33,-237.5 ccw(c1577.33,-137.5) 1648.04,-208.21 1714.46,-141.79 cw(c1785.17,-212.5) 1785.17,-112.5 v4(1787.5,-112.5)
  Bottom Layer w10: v4(1787.5,-112.5) R320.2@1816.54,-112.5
SENS8: R323.2 U71.26 | length 1438.4
  Top Layer w10: v2(1178.15,-157.48) U71.26@1178.15,-115.16
  Bottom Layer w10: v2(1178.15,-157.48) 1178.15,187.5 cw(c1278.15,187.5) 1278.15,287.5 1643.75,287.5 ccw(c1643.75,343.75) 1700,343.75 1700,637.5 ; 1700,638.75 1700,637.5 ; R323.2@1816.54,687.5 1750,687.5 ccw(c1750,637.5) 1700,637.5
SENS9: R208.2 U71.11 | length 1384.1
  Top Layer w10: U71.11@973.43,115.16 973.43,203.67 cw(c1045.05,203.67) 994.4,254.32 ccw(c977.73,270.99) 1001.31,270.99 1001.31,711.11 ccw(c906.66,711.11) 973.59,778.04 965.68,785.95 cw(c1033.72,853.98) 937.5,853.98 937.5,1162.5 cw(c1037.5,1162.5) 1037.5,1262.5 R208.2@1191.54,1262.5
SENS10: R196.2 U71.10 | length 826.6
  Top Layer w10: U71.10@999.02,115.16 999.02,203.67 cw(c1045.05,203.67) 1012.5,236.22 ccw(c977.73,270.99) 1026.9,270.99 1026.9,712.7 cw(c1126.71,712.7) 1126.71,812.5 R196.2@1191.54,812.5
SENS11: R321.2 U71.9 | length 1043.7
  Top Layer w10: U71.9@1024.61,115.16 1024.61,76.77 ccw(c1063.88,76.77) 1063.88,37.49 1224.99,37.49 ccw(c1224.99,75) 1262.5,75 1262.5,187.5 cw(c1362.5,187.5) 1362.5,287.5 v4(1787.5,287.5)
  Bottom Layer w10: v4(1787.5,287.5) R321.2@1816.54,287.5
SENS12: R233.2 U71.8 | length 2285.9
  Top Layer w10: U71.8@1050.2,115.16 v2(1050.2,162.5)
  Int6 (SB) w10: v2(1050.2,162.5) 1050.2,750.92 cw(c1200.2,750.92) 1094.13,856.99 1308.21,1071.07 ccw(c1237.5,1141.78) 1337.5,1141.78 1337.5,1483.24 cw(c1541.76,1483.24) 1541.76,1687.5 1895.96,1687.5 ccw(c1895.96,1787.5) 1966.67,1716.79 v1(2006.25,1756.37)
SENS13: R308.2 U71.7 | length 2390.9
  Top Layer w10: U71.7@1075.79,115.16 v2(1075.79,162.5)
  Int6 (SB) w10: v2(1075.79,162.5) 1075.79,751.51 cw(c1200.79,751.51) 1112.4,839.9 1325.89,1053.39 ccw(c1237.5,1141.78) 1362.5,1141.78 1362.5,1483.24 cw(c1541.76,1483.24) 1541.76,1662.5 1957.33,1662.5 cw(c1957.33,1562.5) 2028.04,1633.21 v1(2105,1556.25)
  Bottom Layer w10: v1(2105,1556.25) 2125,1556.25 R308.2@2125,1545.96
SENS14: Q3.3 Q4.3 R295.2 U71.6 | length 3056.1
  Top Layer w10: U71.6@1101.38,115.16 v2(1101.38,162.5)
  Int6 (SB) w10: v2(1101.38,162.5) 1101.38,752.1 cw(c1201.38,752.1) 1130.67,822.81 1343.57,1035.71 ccw(c1237.5,1141.78) 1387.5,1141.78 1387.5,1483.24 cw(c1541.76,1483.24) 1541.76,1637.5 1921.08,1637.5 cw(c1921.08,1537.5) 1991.79,1608.21 2050,1550 ccw(c2105.84,1605.84) 2105.84,1526.87 v1(2587.5,1526.87)
  Bottom Layer w10: Q4.3@2587.5,1445.62 v1(2587.5,1526.87) Q3.3@2587.5,1633.12
  Bottom Layer w15: R295.2@2520.96,1633.12 Q3.3@2587.5,1633.12
SENS15: R268.2 U71.5 | length 1842.8
  Top Layer w10: U71.5@1126.97,115.16 1126.97,480.88 cw(c1421.09,480.88) 1421.09,775 2212.5,775 ccw(c2212.5,875) 2312.5,875 R268.2@2312.5,941.54
SENS16: R322.2 U71.4 | length 926.7
  Top Layer w10: U71.4@1152.56,115.16 1152.56,273.64 cw(c1252.56,273.64) 1181.85,344.35 1295.71,458.21 cw(c1366.42,387.5) 1366.42,487.5 v4(1787.5,487.5)
  Bottom Layer w10: v4(1787.5,487.5) R322.2@1816.54,487.5
SENS_120f_N: C126.1 C127.1 C138.1 C139.1 P4.1 R298.1 TP29.1 U77.4 U77.9 U77.24 U77.25 U77.35 U77.36 | length 1613.3
  Top Layer w10: v1(1571,1300.79) U77.9@1590.16,1300.79 ; v1(1571,1399.21) U77.4@1590.16,1399.21 ; v1(1833.27,1197.36) U77.24@1833.27,1215.16 ; U77.25@1859.84,1241.73 v1(1878.54,1241.73) ; U77.35@1859.84,1438.58 v1(1878.54,1438.58) v1(1878.54,1458.27) U77.36@1859.84,1458.27
  Int6 (SB) w50: 1896.01,1187.5 TP29.1@2312.5,1187.5
  Bottom Layer w10: C138.1@1525.89,1250 cw(c1545.96,1250) 1531.76,1264.19 1566.49,1298.92 cw(c1571,1294.42) v1(1571,1300.79) ; C139.1@1525.89,1450 ccw(c1547.05,1450) 1532.08,1435.04 1565.72,1401.4 ccw(c1571,1406.68) v1(1571,1399.21) ; v1(1878.54,1241.73) ccw(c1878.54,1271.45) 1899.55,1250.44 C126.1@1925,1275.89 ; v1(1878.54,1458.27) cw(c1878.54,1428.55) 1899.54,1449.57 ; 1899.55,1449.56 C127.1@1925,1424.11
  Bottom Layer w20: P4.1@1125,1750 1196.08,1750 cw(c1196.08,1650) 1266.79,1720.71 1517.67,1469.83 cw(c1497.85,1450) C139.1@1525.89,1450
  Bottom Layer w35: TP29.1@2312.5,1187.5 2418.75,1187.5 cw(c2418.75,1087.5) 2518.75,1087.5 R298.1@2518.75,1070.96
SENS_+15_P: R238.1 R239.1 R244.2 R327.2 | length 880.6
  Top Layer w10: v4(2043.75,-1512.5) R244.2@2068.16,-1512.5
  Top Layer w30: R238.1@1987.5,-1179.04 1970.18,-1179.04 cw(c1970.18,-1133.85) 1925,-1133.85 1925,-1023.4 cw(c1969.36,-1023.4) 1969.36,-979.04 R239.1@1987.5,-979.04
  Int5 (ST) w15: v8(1925,-1075) 1970.71,-1120.71 cw(c1900,-1191.42) 2000,-1191.42 2000,-1426.08 ccw(c2100,-1426.08) 2029.29,-1496.79 2043.75,-1511.25 v4(2043.75,-1512.5)
  Bottom Layer w30: R327.2@1833.46,-1075 v8(1925,-1075)
SENS_-15: R257.2 U79.6 U80.6 | length 361.5
  Top Layer w10: R257.2@2204.04,-1512.5 ccw(c2240.06,-1512.5) 2240.06,-1548.52 U79.6@2245.56,-1548.52 v4(2281.25,-1548.52)
  Top Layer w16: U80.6@2245.56,-1348.52 v4(2281.25,-1348.52)
  Int5 (ST) w10: v4(2281.25,-1548.52) ccw(c2281.25,-1523.96) 2305.81,-1523.96 2305.81,-1373.09 ccw(c2281.25,-1373.09) v4(2281.25,-1348.52)
SENSE.SENS_10_P: C76.1 L3.2 R228.2 R243.2 U92.3 | length 553.6
  Top Layer w10: R243.2@1981.25,995.96 ccw(c2031.15,1045.86) 2031.15,975.3 v1(2041.8,975.3)
  Top Layer w25: R228.2@1775,1111.91 1775,1087.41 ccw(c1799.91,1087.41) 1799.91,1062.5 C76.1@1892.62,1062.5 ; C76.1@1912.5,1064.71 C76.1@1912.5,1082.38 ; R243.2@1981.25,995.96 ccw(c1914.71,995.96) 1914.71,1062.5 C76.1@1892.62,1062.5 ; L3.2@2062.5,1103.35 1963.11,1103.35 ccw(c1963.11,1031.77) C76.1@1912.5,1082.38 ; C76.1@1892.62,1062.5 ccw(c1892.62,1082.38) C76.1@1912.5,1082.38
SENSE.SENS_18_P: C77.2 L4.2 R226.2 R260.2 U78.3 | length 631.9
  Top Layer w7: R226.2@1800.59,1687.5 R226.2@1801.2,1687.5
  Top Layer w10: v1(2270.42,1674.7) cw(c2270.42,1623.02) 2306.97,1659.57 R260.2@2312.5,1654.04
  Top Layer w25: R226.2@1801.2,1687.5 cw(c1801.2,1587.5) 1871.91,1658.21 C77.2@1912.5,1617.62 ccw(c1963.11,1668.23) 1963.11,1596.65 L4.2@2062.5,1596.65 2275,1596.65 ccw(c2275,1634.15) 2312.5,1634.15 R260.2@2312.5,1654.04
SENSE.SENS_25_P: C69.2 L2.2 R211.2 R218.2 U73.3 | length 525.5
  Top Layer w10: R211.2@1269,1575 R211.2@1270.96,1575 1269.85,1573.89 ccw(c1317.07,1526.67) v1@1250.3,1527.21 ; v1@1250.3,1527.21 ccw(c1317.07,1526.67) v1(1250.3,1526.67) v1@1250.3,1527.21
  Top Layer w25: R211.2@1270.96,1575 1275.83,1579.86 cw(c1346.54,1509.15) 1346.54,1609.15 L2.2@1425,1609.15 1541.73,1609.15 cw(c1541.73,1600.89) C69.2@1550,1600.89 cw(c1636.61,1600.89) 1636.61,1687.5 R218.2@1649.41,1687.5
  Bottom Layer w10: U73.3@1250.3,1500.1 v1(1250.3,1526.67)
SENSE.SENS_33_P: C68.2 L1.2 R210.2 R224.2 U72.3 | length 528.9
  Top Layer w10: v1(1250.3,1076.67) cw(c1317.07,1076.67) 1269.85,1123.89 R210.2@1270.96,1125 ; C68.2@1550,1099.11 ccw(c1586.61,1099.11) 1586.61,1062.5 1648.26,1062.5 ccw(c1648.26,1089.24) 1675,1089.24 R224.2@1675,1111.91
  Top Layer w25: R210.2@1270.96,1125 1275.83,1120.14 ccw(c1346.54,1190.85) 1346.54,1090.85 L1.2@1425,1090.85 1530.04,1090.85 ccw(c1530.04,1119.07) C68.2@1550,1099.11
SENSE.SENS_120b_N: R269.2 R271.2 | length 221.7
  Top Layer w10: R271.2@2426.31,1549.31 2449.31,1549.31 ccw(c2449.31,1587.5) 2487.5,1587.5 2487.5,1686.94 cw(c2512.5,1686.94) R269.2@2512.5,1711.94
SENSE.SENS_120b_P: R271.3 R272.2 | length 285.2
  Top Layer w10: R271.3@2426.31,1525.69 2475.69,1525.69 ccw(c2475.69,1587.5) 2537.5,1587.5 2537.5,1686.94 cw(c2562.5,1686.94) R272.2@2562.5,1711.94
SENSE.SENS_120x_N: R270.1 R296.3 | length 237.8
  Top Layer w10: R270.1@2462.5,1363.06 ccw(c2462.5,1394.6) 2484.79,1372.29 v1(2487.5,1375)
  Bottom Layer w10: R296.3@2426.31,1549.31 cw(c2426.31,1488.12) 2487.5,1488.12 v1(2487.5,1375)
SENSE.SENS_120x_P: R296.2 R297.1 | length 239.8
  Top Layer w10: v1(2487.5,1350) 2492.12,1354.62 cw(c2512.5,1334.25) R297.1@2512.5,1363.06
  Bottom Layer w10: R296.2@2426.31,1525.69 cw(c2426.31,1489.5) 2462.5,1489.5 2462.5,1375 ccw(c2487.5,1375) v1(2487.5,1350)
SENSE.SENS_+15: R252.2 R332.1 U81.6 U82.6 | length 984.4
  Top Layer w10: R252.2@2188.09,-912.5 2209.54,-912.5 cw(c2209.54,-948.52) U82.6@2245.56,-948.52 v4(2284.43,-948.52)
  Top Layer w16: U81.6@2245.56,-1148.52 v4(2284.43,-1148.52)
  Bottom Layer w10: R332.1@1708.46,-900 2235.9,-900 cw(c2235.9,-948.52) v4(2284.43,-948.52) ccw(c2284.43,-970.45) 2262.5,-970.45 2262.5,-1126.6 ccw(c2284.43,-1126.6) v4(2284.43,-1148.52)
SENSE.SENS_-15_N: R236.1 R237.1 R251.1 R325.1 R326.2 | length 647
  Top Layer w16: R237.1@1987.5,-1379.04 cw(c2054.04,-1379.04) 2054.04,-1312.5 R251.1@2136.91,-1312.5
  Top Layer w30: R236.1@1987.5,-1579.04 1954.04,-1579.04 cw(c1954.04,-1550) v8(1925,-1550) 1925,-1442.83 1925,-1421.9 cw(c1967.89,-1421.92) 1967.89,-1379.04 R237.1@1987.5,-1379.04
  Bottom Layer w20: R326.2@1837.5,-1545.96 cw(c1833.46,-1545.96) R326.2@1833.46,-1550 ccw(c1823.72,-1540.26) 1837.5,-1540.26 R325.1@1837.5,-1483.46
  Bottom Layer w30: R326.2@1833.46,-1550 1837.5,-1550 v8(1925,-1550)
SENSE.SENS_AVCC: R254.2 R334.1 U84.6 | length 713.4
  Top Layer w10: R254.2@2188.09,-512.5 2209.54,-512.5 cw(c2209.54,-548.52) U84.6@2245.56,-548.52 v4(2284.43,-548.52)
  Bottom Layer w10: R334.1@1708.46,-512.5 2248.4,-512.5 cw(c2248.4,-548.52) v4(2284.43,-548.52)
SENSE.SENS_AVDD1V8: R248.1 R321.1 U87.6 U88.6 | length 777.3
  Top Layer w10: R248.1@2188.09,87.5 2209.54,87.5 cw(c2209.54,51.48) U87.6@2245.56,51.48 v4(2284.43,51.48) ; U88.6@2245.56,251.48 v4(2284.43,251.48)
  Bottom Layer w10: R321.1@1883.46,287.5 2248.4,287.5 cw(c2248.4,251.48) v4(2284.43,251.48) v4(2284.43,51.48)
SENSE.SENS_AVDD5V0: R249.1 R322.1 U89.6 | length 538.4
  Top Layer w10: R249.1@2188.09,487.5 2209.54,487.5 cw(c2209.54,451.48) U89.6@2245.56,451.48 v4(2284.43,451.48)
  Bottom Layer w10: R322.1@1883.46,487.5 2248.4,487.5 cw(c2248.4,451.48) v4(2284.43,451.48)
SENSE.SENS_AVTT: R253.2 R333.1 U83.6 | length 713.4
  Top Layer w10: R253.2@2188.09,-712.5 2209.54,-712.5 cw(c2209.54,-748.52) U83.6@2245.56,-748.52 v4(2284.43,-748.52)
  Bottom Layer w10: R333.1@1708.46,-712.5 2248.4,-712.5 cw(c2248.4,-748.52) v4(2284.43,-748.52)
SENSE.SENS_DVDD1V8: R247.1 R320.1 U85.6 U86.6 | length 777.3
  Top Layer w10: R247.1@2188.09,-312.5 2209.54,-312.5 cw(c2209.54,-348.52) U85.6@2245.56,-348.52 v4(2284.43,-348.52) ; U86.6@2245.56,-148.52 v4(2284.43,-148.52)
  Bottom Layer w10: R320.1@1883.46,-112.5 2248.4,-112.5 cw(c2248.4,-148.52) v4(2284.43,-148.52) v4(2284.43,-348.52)
SENSE.SENS_DVDD5V0: R250.1 R323.1 U90.6 | length 538.4
  Top Layer w10: R250.1@2188.09,687.5 2209.54,687.5 cw(c2209.54,651.48) U90.6@2245.56,651.48 v4(2284.43,651.48)
  Bottom Layer w10: R323.1@1883.46,687.5 2248.4,687.5 cw(c2248.4,651.48) v4(2284.43,651.48)
SMCLK: P2.B5
SMDAT: P2.B6
SQSPI.XMUX0: U50.K1 U68.12 | length 468.9
  Top Layer w5: U50.K1@413.39,-59.06 487.21,-59.06 cw(c487.21,-142.72) 570.87,-142.72 ccw(c644.69,-142.72) 644.69,-216.54 ccw(c644.69,-145.67) 715.55,-145.67 U68.12@715.55,-109.25
SQSPI.XMUX1: U50.L1 U68.11 | length 443.3
  Top Layer w5: U50.L1@413.39,-19.68 461.61,-19.68 cw(c461.61,-148.62) 590.55,-148.62 ccw(c638.78,-148.62) 638.78,-196.85 ccw(c638.78,-145.67) 689.96,-145.67 U68.11@689.96,-109.25
SQSPI.XMUX2: U50.M1 U68.10 | length 428.3
  Top Layer w5: U50.M1@413.39,19.69 460.63,19.69 cw(c460.63,-129.92) 610.24,-129.92 610.24,-154.53 ccw(c632.87,-154.53) 632.87,-177.17 ccw(c632.87,-145.67) 664.37,-145.67 U68.10@664.37,-109.25
SQSPI.XMUX3: U50.J1 U68.13 | length 494.5
  Top Layer w5: U50.J1@413.39,-98.43 512.8,-98.43 cw(c512.8,-136.81) 551.18,-136.81 ccw(c650.59,-136.81) 650.59,-236.22 ccw(c650.59,-145.67) 741.14,-145.67 U68.13@741.14,-109.25
SW+2V5: L9.1 L10.1 R261.2 R262.2 R263.2 R264.2 R301.1 | length 713.8
  Top Layer w30: R261.2@2318.75,-358.07 v9(2318.75,-325) R262.2@2318.75,-291.93 ; R263.2@2318.75,41.93 v9(2318.75,75) R264.2@2318.75,108.07
  Int5 (ST) w35: v9@2325,-325 v9@2325,75
  Bottom Layer w30: v9(2337.5,-806.25) 2337.5,-771.91 2348.09,-761.32 L9.1@2350,-761.32 ; v9(2337.5,-606.25) 2337.5,-571.91 2348.09,-561.32 L10.1@2350,-561.32
  Bottom Layer w35: v9@2325,-325 R301.1@2404.04,-325
SW+6V: R265.2 R266.2 R302.1 | length 162.1
  Top Layer w30: R265.2@2318.75,433.46 v8(2318.75,475) R266.2@2318.75,510.1 ; R266.2@2318.75,516.54 R266.2@2318.85,510.1
  Bottom Layer w35: v8@2325,475 R302.1@2404.04,475
SW+16V: C86.2 C113.2 D5.2 R274.2 R300.2 TP36.1 | length 445.2
  Bottom Layer w35: C113.2@2467.62,-1018.75 cw(c2459.54,-1026.83) 2470.96,-1026.83 R300.2@2470.96,-1112.5
  Bottom Layer w60: C113.2@2467.62,-1018.75 2533.58,-1018.75 ccw(c2533.58,-918.75) 2604.29,-989.46 TP36.1@2750,-843.75
SW-16V: C92.1 C112.1 L6.3 R273.1 R299.2 TP33.1 | length 449.3
  Bottom Layer w35: C112.1@2467.62,-1518.75 cw(c2459.54,-1526.83) 2470.96,-1526.83 R299.2@2470.96,-1612.5
  Bottom Layer w60: C112.1@2467.62,-1518.75 2502.33,-1518.75 cw(c2502.33,-1618.75) 2573.04,-1548.04 TP33.1@2743.75,-1718.75
  other v2: 2860.93,-1754.73 2823.06,-1753.87 2898.06,-1753.87 2841.81,-1735.12 2879.31,-1735.12 2898.06,-1717.62 2823.06,-1716.37 2860.56,-1716.37 2841.81,-1697.62 2879.31,-1697.62 2823.06,-1678.87 2860.56,-1678.87 2898.06,-1678.87
TCK_FPGA: R371.2 U50.V12 | length 269.4
  Top Layer w5: v3(-39.37,275.59) U50.V12@-19.68,255.91
  Bottom Layer w5: R371.2@-59.06,505.91 -59.06,295.28 ccw(c-39.37,295.28) v3(-39.37,275.59)
TCK_JTAG: P3.6 R371.1 | length 1614.5
  Bottom Layer w5: P3.6@-817.52,1628.74 cw(c-817.52,1588.78) -777.56,1588.78 -777.56,1535.25 ccw(c-747.92,1535.25) -747.92,1505.61 -411.02,1505.61 cw(c-411.02,1358.36) -263.78,1358.36 -263.78,787.4 ccw(c-202,787.4) -245.68,743.72 R371.1@-59.06,557.09
TDI_FPGA: R375.2 U50.R13 | length 436.5
  Top Layer w5: v3(-78.74,157.48) U50.R13@-59.05,137.8
  Bottom Layer w5: R375.2@-177.17,505.91 -177.17,246.54 ccw(c-88.11,246.54) -88.11,157.48 v3(-78.74,157.48)
TDI_JTAG: P3.10 R375.1 | length 2157.1
  Bottom Layer w5: P3.10@-660.04,1628.74 -681.14,1649.84 ccw(c-751.85,1579.13) -751.85,1679.13 -968.53,1679.13 ccw(c-968.53,1633.88) -1013.78,1633.88 -1013.78,1516.18 ccw(c-955.97,1516.18) -955.97,1458.36 -411.02,1458.36 cw(c-411.02,1358.36) -311.02,1358.36 -311.02,751.94 ccw(c-163.78,751.94) -267.9,647.82 R375.1@-177.17,557.09
TDO_FPGA: R372.2 U50.U13 | length 308.8
  Top Layer w5: v3(-78.74,236.22) U50.U13@-59.05,216.54
  Bottom Layer w5: R372.2@-98.43,505.91 -98.43,255.91 ccw(c-78.74,255.91) v3(-78.74,236.22)
TDO_JTAG: P3.8 R372.1 | length 1799.1
  Bottom Layer w5: P3.8@-738.78,1628.74 -759.94,1649.9 ccw(c-797.24,1612.6) -797.24,1665.35 -831.76,1665.35 ccw(c-831.76,1640.82) -856.3,1640.71 -856.3,1535.19 ccw(c-810.97,1535.19) -810.97,1489.86 -411.02,1489.86 cw(c-411.02,1358.36) -279.53,1358.36 -279.53,786.13 ccw(c-163.78,786.13) -245.63,704.29 R372.1@-98.43,557.09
